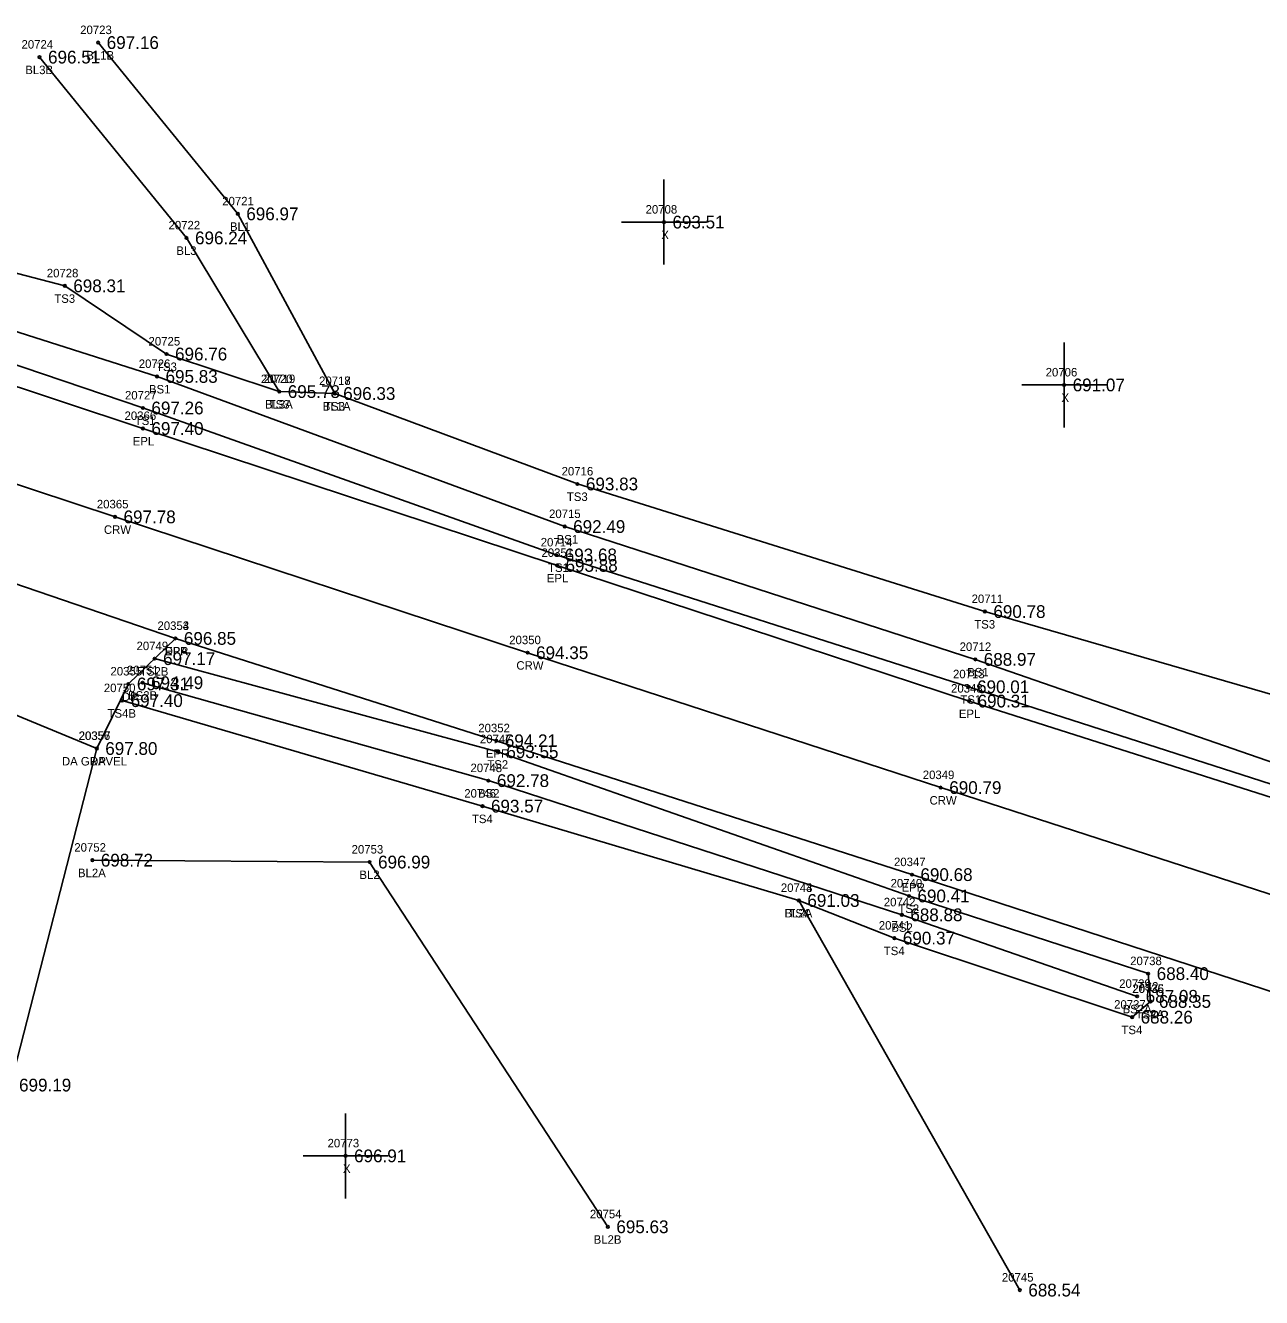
# Model space of a CAD drawing. Extents: x 1655675 to 1657082, y 1004080 to 1005193.
# Drawn here: x 1655788.1 to 1655933.5, y 1004723.9 to 1004873.5 of the extents above; entities that cross this region are included whole.
import ezdxf

# ---------------------------------------------------------------- set-up
doc = ezdxf.new("R2010")
doc.units = 0
for name, color, linetype in [('RD_DTM_BkLn1', 7, 'Continuous'), ('RD_DTM_BkLn2', 7, 'Continuous'), ('RD_DTM_BkLn_txCode', 7, 'Continuous'), ('RD_EX_Driveway', 7, 'Continuous'), ('RD_EX_Driveway_txCode', 7, 'Continuous'), ('RD_EX_Misc', 7, 'Continuous'), ('RD_EX_Misc_txCode', 7, 'Continuous'), ('RD_EX_Road', 7, 'Continuous'), ('RD_EX_Road_txCode', 7, 'Continuous'), ('RD_EX_TX_Driveway_ELEV', 7, 'Continuous'), ('RD_EX_TX_Misc_ELEV', 7, 'Continuous'), ('RD_EX_TX_Road_ELEV', 7, 'Continuous'), ('RD_HC_Survey_ELEV', 7, 'Continuous'), ('RD_HC_Survey_txCode', 7, 'Continuous'), ('RD_SMD_Locator', 7, 'Continuous')]:
    doc.layers.add(name, color=color, linetype=linetype)

msp = doc.modelspace()

# ---------------------------------------------------------------- linework, layer by layer
at = {"layer": 'RD_DTM_BkLn1'}
msp.add_line((1655879.07, 1004770.57), (1655905.06, 1004724.73), dxfattribs=at)
for points in [[(1655824.47, 1004830.21), (1655813.07, 1004851.35), (1655796.65, 1004871.5)], [(1655817.95, 1004830.44), (1655807.04, 1004848.52), (1655789.75, 1004869.79)], [(1656361.94, 1004629.69), (1656332.67, 1004639.45), (1656283.94, 1004655.24), (1656235.41, 1004671.18), (1656186.64, 1004687.32), (1656138.18, 1004703.47), (1656089.58, 1004719.78), (1656041.19, 1004735.88), (1655992.79, 1004752.04), (1655944.27, 1004768.13), (1655895.76, 1004783.85), (1655847.16, 1004799.72), (1655798.63, 1004815.7), (1655750.32, 1004831.65), (1655701.73, 1004847.83)], [(1655795.96, 1004775.31), (1655828.57, 1004775.09), (1655856.6, 1004732.18)]]:
    msp.add_lwpolyline(points, dxfattribs=at)
at = {"layer": 'RD_DTM_BkLn2'}
for points in [[(1656169.82, 1004711.08), (1656140.99, 1004718.68), (1656095.33, 1004733.78), (1656045.66, 1004750.66), (1655997.73, 1004765.48), (1655948.28, 1004782.13), (1655899.82, 1004798.93), (1655851.52, 1004814.56), (1655803.57, 1004832.22), (1655755.82, 1004847.44), (1655708.15, 1004866.52)], [(1656170.81, 1004710.38), (1656169.05, 1004714.04), (1656155.08, 1004721.39), (1656138.53, 1004726.1), (1656123.28, 1004729.96), (1656095.95, 1004735.19), (1656083.94, 1004739.91), (1656074.75, 1004751.62), (1656052.43, 1004759.33), (1656035.39, 1004767.92), (1656020.14, 1004775.42), (1656002.81, 1004778.08), (1655951.09, 1004790.04), (1655900.95, 1004804.56), (1655853.02, 1004819.57), (1655824.47, 1004830.21), (1655817.95, 1004830.44), (1655804.69, 1004834.86), (1655792.72, 1004842.88), (1655757.63, 1004852.03), (1655728.3, 1004865.14)], [(1656170.81, 1004710.38), (1656167.78, 1004708.02), (1656140.38, 1004715.48), (1656094.47, 1004730.71), (1656044.88, 1004747.29), (1655996.79, 1004763.35), (1655947.9, 1004779.96), (1655899.03, 1004795.71), (1655850.53, 1004811.22), (1655801.91, 1004828.51), (1655755.02, 1004844.41), (1655705.18, 1004859.33)], [(1655920.42, 1004758.69), (1655920.16, 1004761.96), (1655892.02, 1004771.1), (1655843.66, 1004788.07), (1655803.28, 1004799.02)], [(1655918.87, 1004759.29), (1655891.18, 1004768.88), (1655842.55, 1004784.67), (1655801.87, 1004796.19)], [(1655920.42, 1004758.69), (1655918.27, 1004756.84), (1655890.3, 1004766.14), (1655879.07, 1004770.57), (1655841.85, 1004781.67), (1655799.47, 1004794.08)]]:
    msp.add_lwpolyline(points, dxfattribs=at)
at = {"layer": 'RD_EX_Driveway'}
msp.add_line((1655796.48, 1004788.45), (1655786.34, 1004748.85), dxfattribs=at)
msp.add_lwpolyline([(1655805.73, 1004801.4), (1655800.2, 1004796.04), (1655796.48, 1004788.45), (1655780.61, 1004794.99), (1655780.95, 1004804.46), (1655779.22, 1004810.43)], dxfattribs=at)
at = {"layer": 'RD_EX_Misc'}
for p, q in [((1655863.2, 1004845.38), (1655863.2, 1004855.38)), ((1655858.2, 1004850.38), (1655868.2, 1004850.38)), ((1655910.28, 1004826.22), (1655910.28, 1004836.22)), ((1655905.28, 1004831.22), (1655915.28, 1004831.22)), ((1655825.75, 1004735.52), (1655825.75, 1004745.52)), ((1655820.75, 1004740.52), (1655830.75, 1004740.52))]:
    msp.add_line(p, q, dxfattribs=at)
at = {"layer": 'RD_EX_Road'}
for points in [[(1656365.12, 1004639.99), (1656336.04, 1004649.34), (1656302.55, 1004660.37), (1656279.15, 1004668.23), (1656240.07, 1004681.05), (1656188.23, 1004698.03), (1656166.72, 1004705.51), (1656141.16, 1004714.06), (1656093.11, 1004730.11), (1656044.16, 1004746.75), (1655996.36, 1004762.45), (1655947.2, 1004778.68), (1655899.09, 1004794.03), (1655850.62, 1004809.99), (1655801.91, 1004826.1), (1655753.09, 1004842.31), (1655704.25, 1004858.1)], [(1656358.5, 1004619.83), (1656328.78, 1004629.48), (1656280.77, 1004645.39), (1656247.66, 1004656.11), (1656244.5, 1004656.52), (1656222.03, 1004663.57), (1656217.65, 1004665.96), (1656183.42, 1004677.32), (1656134.59, 1004693.72), (1656086.19, 1004709.75), (1656037.58, 1004726.13), (1655989.57, 1004741.99), (1655940.62, 1004757.88), (1655892.37, 1004773.61), (1655843.48, 1004789.36), (1655805.73, 1004801.4), (1655779.22, 1004810.43), (1655768.8, 1004813.1), (1655744.59, 1004822.13), (1655698.83, 1004837.65)]]:
    msp.add_lwpolyline(points, dxfattribs=at)
at = {"layer": 'RD_SMD_Locator'}
for centre in [(1655796.65, 1004871.5), (1655789.75, 1004869.79), (1655813.07, 1004851.35), (1655863.2, 1004850.38), (1655807.04, 1004848.52), (1655792.72, 1004842.88), (1655804.69, 1004834.86), (1655803.57, 1004832.22), (1655817.95, 1004830.44), (1655817.95, 1004830.44), (1655824.47, 1004830.21), (1655824.47, 1004830.21), (1655910.28, 1004831.22), (1655801.91, 1004828.51), (1655801.91, 1004826.1), (1655853.02, 1004819.57), (1655798.63, 1004815.7), (1655851.52, 1004814.56), (1655850.53, 1004811.22), (1655850.62, 1004809.99), (1655900.95, 1004804.56), (1655805.73, 1004801.4), (1655805.73, 1004801.4), (1655803.28, 1004799.02), (1655847.16, 1004799.72), (1655899.82, 1004798.93), (1655800.2, 1004796.04), (1655801.87, 1004796.19), (1655899.03, 1004795.71), (1655799.47, 1004794.08), (1655899.09, 1004794.03), (1655796.48, 1004788.45), (1655796.48, 1004788.45), (1655843.48, 1004789.36), (1655843.66, 1004788.07), (1655842.55, 1004784.67), (1655895.76, 1004783.85), (1655841.85, 1004781.67), (1655795.96, 1004775.31), (1655828.57, 1004775.09), (1655892.37, 1004773.61), (1655879.07, 1004770.57), (1655879.07, 1004770.57), (1655892.02, 1004771.1), (1655891.18, 1004768.88), (1655890.3, 1004766.14), (1655920.16, 1004761.96), (1655918.87, 1004759.29), (1655920.42, 1004758.69), (1655920.42, 1004758.69), (1655918.27, 1004756.84), (1655825.75, 1004740.52), (1655856.6, 1004732.18), (1655905.06, 1004724.73)]:
    msp.add_circle(centre, 0.15, dxfattribs=at)

# ---------------------------------------------------------------- texts
at = {"layer": 'RD_DTM_BkLn_txCode'}
for s, p in [('20723', (1655794.53, 1004872.5)), ('20724', (1655787.63, 1004870.79)), ('BL1B', (1655795.25, 1004869.5)), ('BL3B', (1655788.07, 1004867.79)), ('20721', (1655811.24, 1004852.35)), ('20722', (1655804.92, 1004849.52)), ('BL1', (1655812.15, 1004849.35)), ('BL3', (1655805.84, 1004846.52)), ('20728', (1655790.6, 1004843.88)), ('TS3', (1655791.48, 1004840.88)), ('20725', (1655802.57, 1004835.86)), ('20726', (1655801.42, 1004833.22)), ('TS3', (1655803.45, 1004832.86)), ('20720', (1655815.79, 1004831.44)), ('20719', (1655816.11, 1004831.44)), ('20717', (1655822.63, 1004831.21)), ('20718', (1655822.63, 1004831.21)), ('20727', (1655799.8, 1004829.51)), ('BS1', (1655802.62, 1004830.22)), ('BL3A', (1655816.26, 1004828.44)), ('TS3', (1655816.7, 1004828.44)), ('BL1A', (1655823.06, 1004828.21)), ('TS3', (1655823.22, 1004828.21)), ('TS1', (1655800.95, 1004826.51)), ('20716', (1655851.16, 1004820.57)), ('TS3', (1655851.78, 1004817.57)), ('20715', (1655849.68, 1004815.56)), ('20714', (1655848.7, 1004812.22)), ('BS1', (1655850.57, 1004812.56)), ('TS1', (1655849.57, 1004809.22)), ('20711', (1655899.39, 1004805.56)), ('TS3', (1655899.7, 1004802.56)), ('20749', (1655801.16, 1004800.02)), ('20712', (1655897.98, 1004799.93)), ('20751', (1655800.03, 1004797.19)), ('TS2B', (1655801.56, 1004797.02)), ('20713', (1655897.2, 1004796.71)), ('BS1', (1655898.87, 1004796.93)), ('20750', (1655797.31, 1004795.08)), ('BS2B', (1655800.16, 1004794.19)), ('TS1', (1655898.07, 1004793.71)), ('TS4B', (1655797.75, 1004792.08)), ('20747', (1655841.55, 1004789.07)), ('TS2', (1655842.42, 1004786.07)), ('20748', (1655840.44, 1004785.67)), ('20746', (1655839.71, 1004782.67)), ('BS2', (1655841.33, 1004782.67)), ('TS4', (1655840.61, 1004779.67)), ('20752', (1655793.84, 1004776.31)), ('20753', (1655826.46, 1004776.09)), ('BL2A', (1655794.27, 1004773.31)), ('BL2', (1655827.37, 1004773.09)), ('20743', (1655876.95, 1004771.57)), ('20744', (1655876.95, 1004771.57)), ('20740', (1655889.86, 1004772.1)), ('20742', (1655889.06, 1004769.88)), ('BL2A', (1655877.38, 1004768.57)), ('TS4', (1655877.83, 1004768.57)), ('TS2', (1655890.77, 1004769.1)), ('20741', (1655888.47, 1004767.14)), ('BS2', (1655889.95, 1004766.88)), ('TS4', (1655889.06, 1004764.14)), ('20738', (1655918.04, 1004762.96)), ('20739', (1655916.75, 1004760.29)), ('20736', (1655918.28, 1004759.69)), ('20735', (1655918.31, 1004759.69)), ('TS2', (1655918.91, 1004759.96)), ('20737', (1655916.15, 1004757.84)), ('BS2A', (1655917.15, 1004757.29)), ('TS2A', (1655918.69, 1004756.69)), ('TS4A', (1655918.69, 1004756.69)), ('TS4', (1655917.02, 1004754.84)), ('20754', (1655854.49, 1004733.18)), ('BL2B', (1655854.93, 1004730.18)), ('20745', (1655902.95, 1004725.73))]:
    msp.add_text(s, height=1, dxfattribs=at).set_placement(p)
at = {"layer": 'RD_EX_Driveway_txCode'}
for s, p in [('20354', (1655803.62, 1004802.4)), ('DPA', (1655804.47, 1004799.4)), ('20355', (1655798.09, 1004797.04)), ('DP', (1655799.43, 1004794.04)), ('20356', (1655794.34, 1004789.45)), ('20357', (1655794.37, 1004789.45)), ('DA GRAVEL', (1655792.38, 1004786.45)), ('DP', (1655795.7, 1004786.45))]:
    msp.add_text(s, height=1, dxfattribs=at).set_placement(p)
at = {"layer": 'RD_EX_Misc_txCode'}
for s, p in [('20708', (1655861.04, 1004851.38)), ('X', (1655862.89, 1004848.38)), ('20706', (1655908.1, 1004832.22)), ('X', (1655909.96, 1004829.22)), ('20773', (1655823.63, 1004741.52)), ('X', (1655825.44, 1004738.52))]:
    msp.add_text(s, height=1, dxfattribs=at).set_placement(p)
at = {"layer": 'RD_EX_Road_txCode'}
for s, p in [('20366', (1655799.75, 1004827.1)), ('EPL', (1655800.71, 1004824.1)), ('20351', (1655848.79, 1004810.99)), ('EPL', (1655849.42, 1004807.99)), ('20353', (1655803.62, 1004802.4)), ('EPR', (1655804.51, 1004799.4)), ('20348', (1655896.97, 1004795.03)), ('EPL', (1655897.89, 1004792.03)), ('20352', (1655841.36, 1004790.36)), ('EPR', (1655842.25, 1004787.36)), ('20347', (1655890.26, 1004774.61)), ('EPR', (1655891.15, 1004771.61))]:
    msp.add_text(s, height=1, dxfattribs=at).set_placement(p)
at = {"layer": 'RD_EX_TX_Driveway_ELEV'}
for s, p in [('696.85', (1655806.73, 1004800.65)), ('697.31', (1655801.2, 1004795.29)), ('697.80', (1655797.48, 1004787.7)), ('697.80', (1655797.48, 1004787.7)), ('699.19', (1655787.34, 1004748.1))]:
    msp.add_text(s, height=1.5, dxfattribs=at).set_placement(p)
at = {"layer": 'RD_EX_TX_Misc_ELEV'}
for s, p in [('697.16', (1655797.65, 1004870.75)), ('696.51', (1655790.75, 1004869.04)), ('696.97', (1655814.07, 1004850.6)), ('693.51', (1655864.2, 1004849.63)), ('696.24', (1655808.04, 1004847.77)), ('698.31', (1655793.72, 1004842.13)), ('696.76', (1655805.69, 1004834.11)), ('695.83', (1655804.57, 1004831.47)), ('691.07', (1655911.28, 1004830.47)), ('695.78', (1655818.95, 1004829.69)), ('695.78', (1655818.95, 1004829.69)), ('696.33', (1655825.47, 1004829.46)), ('696.33', (1655825.47, 1004829.46)), ('697.26', (1655802.91, 1004827.76)), ('693.83', (1655854.02, 1004818.82)), ('692.49', (1655852.52, 1004813.81)), ('693.68', (1655851.53, 1004810.47)), ('690.78', (1655901.95, 1004803.81)), ('697.17', (1655804.28, 1004798.27)), ('688.97', (1655900.82, 1004798.18)), ('694.49', (1655802.87, 1004795.44)), ('690.01', (1655900.03, 1004794.96)), ('697.40', (1655800.47, 1004793.33)), ('693.55', (1655844.66, 1004787.32)), ('692.78', (1655843.55, 1004783.92)), ('693.57', (1655842.85, 1004780.92)), ('698.72', (1655796.96, 1004774.56)), ('696.99', (1655829.57, 1004774.34)), ('691.03', (1655880.07, 1004769.82)), ('691.03', (1655880.07, 1004769.82)), ('690.41', (1655893.02, 1004770.35)), ('688.88', (1655892.18, 1004768.13)), ('690.37', (1655891.3, 1004765.39)), ('688.40', (1655921.16, 1004761.21)), ('687.08', (1655919.87, 1004758.54)), ('688.35', (1655921.42, 1004757.94)), ('688.35', (1655921.42, 1004757.94)), ('688.26', (1655919.27, 1004756.09)), ('696.91', (1655826.75, 1004739.77)), ('695.63', (1655857.6, 1004731.43)), ('688.54', (1655906.06, 1004723.98))]:
    msp.add_text(s, height=1.5, dxfattribs=at).set_placement(p)
at = {"layer": 'RD_EX_TX_Road_ELEV'}
for s, p in [('697.40', (1655802.91, 1004825.35)), ('693.88', (1655851.62, 1004809.24)), ('696.85', (1655806.73, 1004800.65)), ('690.31', (1655900.09, 1004793.28)), ('694.21', (1655844.48, 1004788.61)), ('690.68', (1655893.37, 1004772.86))]:
    msp.add_text(s, height=1.5, dxfattribs=at).set_placement(p)
at = {"layer": 'RD_HC_Survey_ELEV'}
for s, p in [('697.78', (1655799.63, 1004814.95)), ('694.35', (1655848.16, 1004798.97)), ('690.79', (1655896.76, 1004783.1))]:
    msp.add_text(s, height=1.5, dxfattribs=at).set_placement(p)
at = {"layer": 'RD_HC_Survey_txCode'}
for s, p in [('20365', (1655796.49, 1004816.7)), ('CRW', (1655797.32, 1004813.7)), ('20350', (1655845, 1004800.72)), ('CRW', (1655845.84, 1004797.72)), ('20349', (1655893.64, 1004784.85)), ('CRW', (1655894.44, 1004781.85))]:
    msp.add_text(s, height=1, dxfattribs=at).set_placement(p)

doc.saveas('drawing.dxf')
